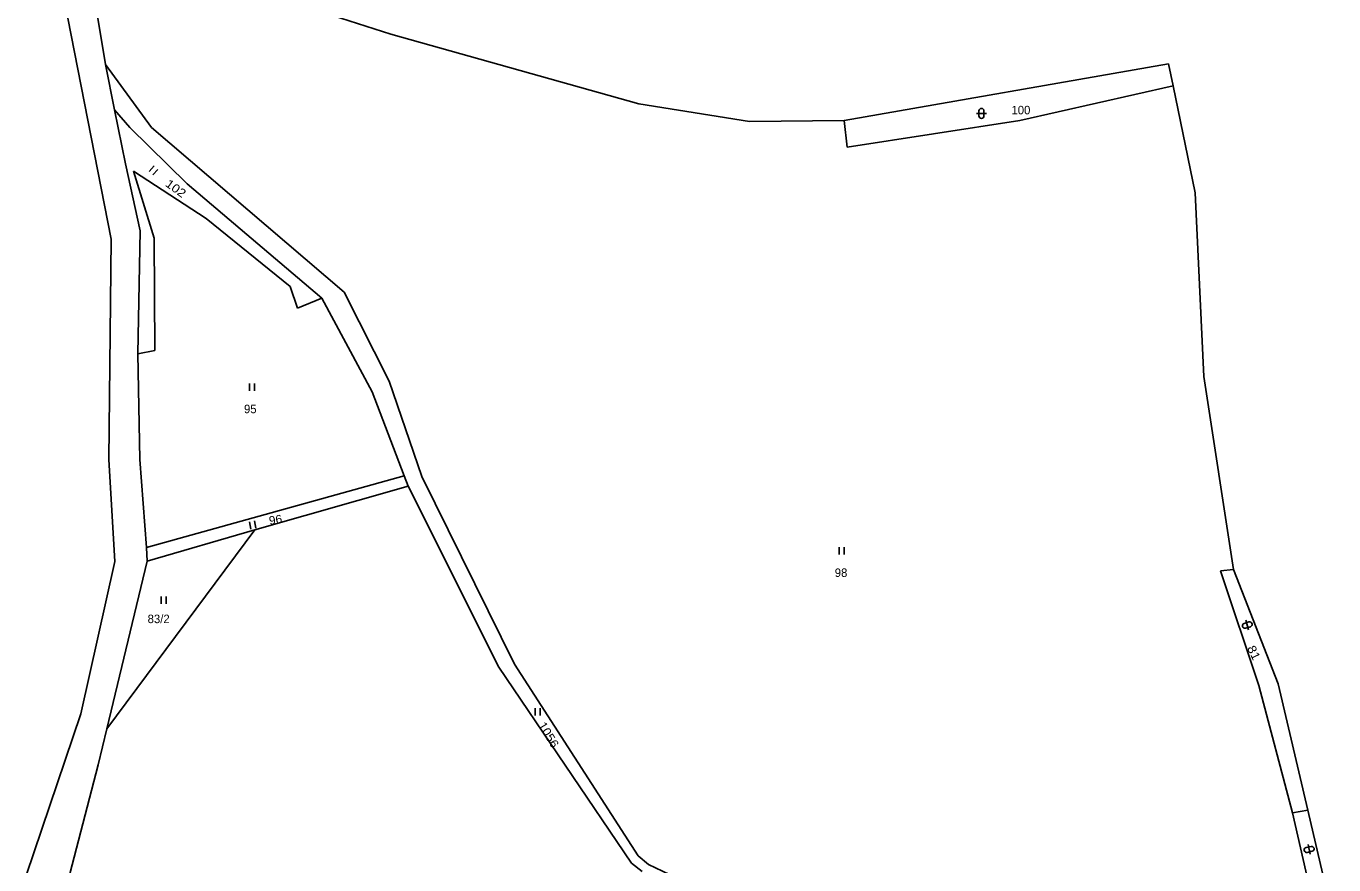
# Model space of a CAD drawing. Extents: x -744132 to -742433, y -984679 to -982287.
# Drawn here: x -742697.6 to -742435.6, y -984423.2 to -984255 of the extents above; entities that cross this region are included whole.
import ezdxf

# ---------------------------------------------------------------- set-up
doc = ezdxf.new("R2010")
doc.units = 0
doc.header["$LTSCALE"] = 0.68
doc.layers.add('1', color=7, linetype='Continuous', lineweight=25)
doc.layers.add('3', color=7, linetype='Continuous', lineweight=25)
doc.layers.add('2', color=7, linetype='Continuous')

msp = doc.modelspace()

# ---------------------------------------------------------------- linework, layer by layer
at = {"layer": '1'}
for p, q in [((-742624.53, -984256.61), (-742677.37, -984239.66)), ((-742689.26, -984253.42), (-742680.62, -984297.71)), ((-742681.71, -984262.69), (-742683.36, -984253.03)), ((-742574.86, -984270.58), (-742624.53, -984256.61)), ((-742468.69, -984262.55), (-742533.71, -984273.93)), ((-742467.78, -984266.95), (-742468.69, -984262.55)), ((-742498.51, -984273.9), (-742467.78, -984266.95)), ((-742463.34, -984288.46), (-742467.78, -984266.95)), ((-742552.66, -984274.12), (-742574.86, -984270.58)), ((-742679.9, -984271.77), (-742676.83, -984275.35)), ((-742677.74, -984282.65), (-742679.9, -984271.77)), ((-742676.83, -984275.35), (-742665.35, -984286.65)), ((-742672.51, -984275.36), (-742633.91, -984308.35)), ((-742533.71, -984273.93), (-742552.66, -984274.12)), ((-742533.71, -984273.93), (-742533.11, -984279.28)), ((-742533.11, -984279.28), (-742498.51, -984273.9)), ((-742674.79, -984296.08), (-742677.74, -984282.65)), ((-742676.09, -984284.09), (-742661.56, -984293.55)), ((-742676.09, -984284.09), (-742671.95, -984297.54)), ((-742665.35, -984286.65), (-742638.38, -984309.56)), ((-742461.65, -984325.23), (-742463.34, -984288.46)), ((-742661.56, -984293.55), (-742644.75, -984307.23)), ((-742674.79, -984296.08), (-742675.26, -984320.72)), ((-742680.62, -984297.71), (-742681.06, -984341.88)), ((-742671.95, -984297.54), (-742671.84, -984320.02)), ((-742644.75, -984307.23), (-742643.27, -984311.53)), ((-742643.27, -984311.53), (-742638.38, -984309.56)), ((-742638.38, -984309.56), (-742628.31, -984328.32)), ((-742633.91, -984308.35), (-742624.9, -984326.19)), ((-742671.84, -984320.02), (-742675.26, -984320.72)), ((-742674.83, -984341.9), (-742675.26, -984320.72)), ((-742455.67, -984363.95), (-742461.65, -984325.23)), ((-742628.31, -984328.32), (-742621.86, -984345.19)), ((-742681.06, -984341.88), (-742679.87, -984362.34)), ((-742673.48, -984359.52), (-742674.83, -984341.9)), ((-742673.48, -984359.52), (-742621.86, -984345.19)), ((-742621.86, -984345.19), (-742621.06, -984347.24)), ((-742651.81, -984356.01), (-742621.06, -984347.24)), ((-742621.06, -984347.24), (-742602.88, -984383.55)), ((-742651.81, -984356.01), (-742681.46, -984395.92)), ((-742673.36, -984362.25), (-742651.81, -984356.01)), ((-742673.36, -984362.25), (-742673.48, -984359.52)), ((-742679.87, -984362.34), (-742686.64, -984392.91)), ((-742681.46, -984395.92), (-742673.36, -984362.25)), ((-742455.67, -984363.95), (-742458.3, -984364.22)), ((-742458.3, -984364.22), (-742450.63, -984387.2)), ((-742446.72, -984386.9), (-742455.67, -984363.95)), ((-742602.88, -984383.55), (-742576.33, -984422.81)), ((-742599.78, -984382.93), (-742574.96, -984421.34)), ((-742450.63, -984387.2), (-742443.84, -984412.74)), ((-742440.79, -984412.23), (-742446.72, -984386.9)), ((-742686.64, -984392.91), (-742697.63, -984425.32)), ((-742683.18, -984403.1), (-742681.46, -984395.92)), ((-742688.87, -984424.99), (-742683.18, -984403.1)), ((-742443.84, -984412.74), (-742440.79, -984412.23)), ((-742435.57, -984434.53), (-742440.79, -984412.23)), ((-742443.84, -984412.74), (-742438.78, -984434.87)), ((-742576.33, -984422.81), (-742574.19, -984424.53)), ((-742574.96, -984421.34), (-742572.92, -984423.1)), ((-742572.92, -984423.1), (-742541.44, -984438.02))]:
    msp.add_line(p, q, dxfattribs=at)
for points in [[(-742679.9, -984271.77), (-742681.71, -984262.69), (-742672.51, -984275.36)], [(-742624.9, -984326.19), (-742618.36, -984345.3), (-742599.78, -984382.93)]]:
    msp.add_lwpolyline(points, dxfattribs=at)
at = {"layer": '3'}
for p, q in [((-742507.191, -984272.521), (-742505.189, -984272.521)), ((-742506.691, -984272.021), (-742506.691, -984273.022)), ((-742505.689, -984273.022), (-742505.689, -984272.021)), ((-742672.994, -984284.152), (-742671.971, -984283.055)), ((-742672.261, -984284.834), (-742671.238, -984283.737)), ((-742652.901, -984328.14), (-742652.901, -984326.64)), ((-742651.9, -984328.14), (-742651.9, -984326.64)), ((-742652.581, -984355.837), (-742652.868, -984354.365)), ((-742651.599, -984355.646), (-742651.885, -984354.174)), ((-742534.701, -984360.97), (-742534.701, -984359.47)), ((-742533.7, -984360.97), (-742533.7, -984359.47)), ((-742670.591, -984370.84), (-742670.591, -984369.34)), ((-742669.59, -984370.84), (-742669.59, -984369.34)), ((-742452.577, -984374.476), (-742453.539, -984374.751)), ((-742453.263, -984375.714), (-742452.301, -984375.438)), ((-742453.196, -984374.132), (-742452.644, -984376.057)), ((-742595.651, -984393.24), (-742595.651, -984391.74)), ((-742594.65, -984393.24), (-742594.65, -984391.74)), ((-742440.142, -984419.475), (-742441.117, -984419.7)), ((-742440.892, -984420.676), (-742439.916, -984420.45)), ((-742440.742, -984419.1), (-742440.292, -984421.051))]:
    msp.add_line(p, q, dxfattribs=at)
for centre, start, end in [((-742506.19, -984272.0209), 0, 180), ((-742506.19, -984273.0209), 180, 359.98789), ((-742453.4002, -984375.2324), 106, 285.98789), ((-742452.439, -984374.9568), 286, 106), ((-742441.0037, -984420.1877), 103, 282.98789), ((-742440.0293, -984419.9628), 283, 103)]:
    msp.add_arc(centre, 0.5, start, end, dxfattribs=at)

# ---------------------------------------------------------------- texts
at = {"layer": '2'}
for s, p in [('100', (-742500.18, -984272.695)), ('95', (-742653.98, -984332.615)), ('98', (-742535.59, -984365.445)), ('83/2', (-742673.29, -984374.705))]:
    msp.add_text(s, height=1.7, dxfattribs=at).set_placement(p)
for s, rotation, width, p in [('102', 324, 1.15, (-742669.899, -984286.953)), ('96', 9, 1.05, (-742648.833, -984355.019)), ('81', 296, 1.15, (-742453.001, -984379.696)), ('1056', 301, 1.1, (-742595.084, -984395.138))]:
    msp.add_text(s, height=1.7, rotation=rotation, dxfattribs=dict(at, width=width)).set_placement(p)

doc.saveas('drawing.dxf')
